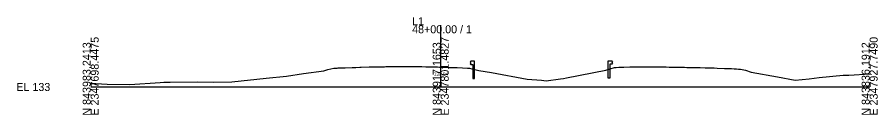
# Model space of a CAD drawing. Extents: x -26 to 2348258, y -10 to 844496.
# Drawn here: x 5143 to 5443.9, y -9.7 to 24.3 of the extents above; entities that cross this region are included whole.
import ezdxf

# ---------------------------------------------------------------- set-up
doc = ezdxf.new("R2010")
doc.units = 0
for name, color, linetype in [('Exist Cross Section Cell', 7, 'Continuous'), ('Exist XS Center Line Elevation Label', 7, 'Continuous'), ('Exist XS Ground Line', 7, 'Continuous'), ('Prop CMT Guardrail Graphics', 7, 'Continuous')]:
    doc.layers.add(name, color=color, linetype=linetype)

msp = doc.modelspace()

# ---------------------------------------------------------------- linework, layer by layer
at = {"layer": 'Exist Cross Section Cell'}
for p, q in [((5291.09, 0), (5291.09, 21.53)), ((5168.69, 0), (5291.09, 0)), ((5291.09, 0), (5441.09, 0))]:
    msp.add_line(p, q, dxfattribs=at)
at = {"layer": 'Exist XS Ground Line'}
msp.add_lwpolyline([(5168.69, 1.16), (5170.47, 1.16), (5174.42, 1.01), (5182.35, 0.85), (5192.95, 1.55), (5194.23, 1.63), (5196.51, 1.63), (5206.11, 1.84), (5211.47, 1.63), (5217.99, 1.8), (5230, 3.02), (5237.16, 3.81), (5243.08, 4.65), (5250.27, 5.66), (5251.62, 6.07), (5253.69, 6.57), (5254.02, 6.55), (5254.36, 6.56), (5254.83, 6.61), (5255.18, 6.63), (5257.17, 6.69), (5257.7, 6.71), (5260.11, 6.79), (5261.41, 6.82), (5262.85, 6.87), (5263.31, 6.88), (5266.03, 6.97), (5267.19, 7.01), (5267.92, 7.02), (5268.99, 7.04), (5269.63, 7.05), (5270.66, 7.07), (5271.45, 7.08), (5271.94, 7.09), (5273.26, 7.11), (5275.31, 7.14), (5276.9, 7.16), (5277.93, 7.18), (5279, 7.18), (5279.59, 7.16), (5280.37, 7.16), (5280.89, 7.16), (5282.56, 7.13), (5283.82, 7.11), (5284.54, 7.1), (5285.91, 7.07), (5286.82, 7.05), (5287.74, 7.03), (5289.16, 7), (5290.02, 6.98), (5291, 6.94), (5292.73, 6.89), (5293.81, 6.85), (5294.95, 6.81), (5295.69, 6.78), (5296.8, 6.74), (5298.68, 6.66), (5300.5, 6.58), (5301.16, 6.55), (5302.02, 6.35), (5304.41, 5.76), (5308.85, 5.01), (5321.3, 2.71), (5326.39, 2.35), (5327.91, 2.1), (5333.03, 2.87), (5334.02, 3), (5335.07, 3.22), (5348.78, 5.84), (5351.84, 6.84), (5352.5, 6.85), (5353.33, 6.89), (5353.76, 6.9), (5354.7, 6.93), (5355.16, 6.94), (5357.17, 6.98), (5358.06, 7), (5358.61, 7), (5360.16, 7.03), (5361.07, 7.03), (5361.57, 7.04), (5362.06, 7.04), (5363.07, 7.05), (5364.04, 7.05), (5365.53, 7.04), (5366.99, 7.03), (5367.95, 7.02), (5369.96, 6.98), (5370.98, 6.96), (5372.57, 6.93), (5373.08, 6.92), (5374.27, 6.89), (5375.92, 6.87), (5376.38, 6.86), (5377.13, 6.85), (5378.22, 6.83), (5378.88, 6.83), (5381.81, 6.77), (5383.62, 6.73), (5384.83, 6.69), (5385.81, 6.67), (5386.3, 6.65), (5386.75, 6.64), (5387.79, 6.6), (5390.3, 6.5), (5391.04, 6.48), (5392.77, 6.4), (5393.74, 6.36), (5394.51, 6.32), (5395.22, 6.26), (5395.92, 6.24), (5397.64, 5.81), (5399.65, 5.12), (5408.86, 3.5), (5415.06, 2.35), (5419.95, 2.86), (5421.66, 3.02), (5423.43, 3.31), (5431.83, 4.09), (5432.59, 4.11), (5433.77, 4.17), (5441.09, 4.56)], dxfattribs=at)
at = {"layer": 'Prop CMT Guardrail Graphics'}
for p, q in [((5349.6, 3.13), (5349.6, 9.13)), ((5349.6, 9.13), (5350.94, 9.13)), ((5350.94, 9.13), (5351.21, 8.84)), ((5301.62, 9), (5301.35, 8.71)), ((5301.35, 8.71), (5301.62, 8.42)), ((5301.62, 8.42), (5301.35, 8.13)), ((5301.35, 8.13), (5301.62, 7.84)), ((5302.95, 9), (5301.62, 9)), ((5301.62, 7.84), (5302.29, 7.84)), ((5302.29, 7.84), (5302.29, 3)), ((5302.95, 3), (5302.95, 9)), ((5350.94, 7.96), (5350.27, 7.96)), ((5350.27, 7.96), (5350.27, 3.13)), ((5351.21, 8.84), (5350.94, 8.55)), ((5350.94, 8.55), (5351.21, 8.26)), ((5351.21, 8.26), (5350.94, 7.96)), ((5350.27, 3.13), (5349.6, 3.13)), ((5302.29, 3), (5302.95, 3))]:
    msp.add_line(p, q, dxfattribs=at)

# ---------------------------------------------------------------- texts
at = {"layer": 'Exist Cross Section Cell'}
for s, p in [('L1', (5281.09, 21.53)), ('48+00.00 / 1', (5281.09, 18.73)), ('EL 133', (5142.69, -1.4))]:
    msp.add_text(s, height=2.8, dxfattribs=at).set_placement(p)
for s, p in [('N 843983.2413', (5168.69, -10)), ('E 2347698.4475', (5171.49, -10)), ('N 843917.1653', (5291.09, -10)), ('E 2347801.4827', (5293.89, -10)), ('N 843836.1912', (5441.09, -10)), ('E 2347927.7490', (5443.89, -10))]:
    msp.add_text(s, height=2.8, rotation=90, dxfattribs=at).set_placement(p)
at = {"layer": 'Exist XS Center Line Elevation Label'}
msp.add_text('139.94', height=1.2, dxfattribs=at).set_placement((5288.64, 3.89))

doc.saveas('drawing.dxf')
